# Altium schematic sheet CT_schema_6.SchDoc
size 277 x 170 mm
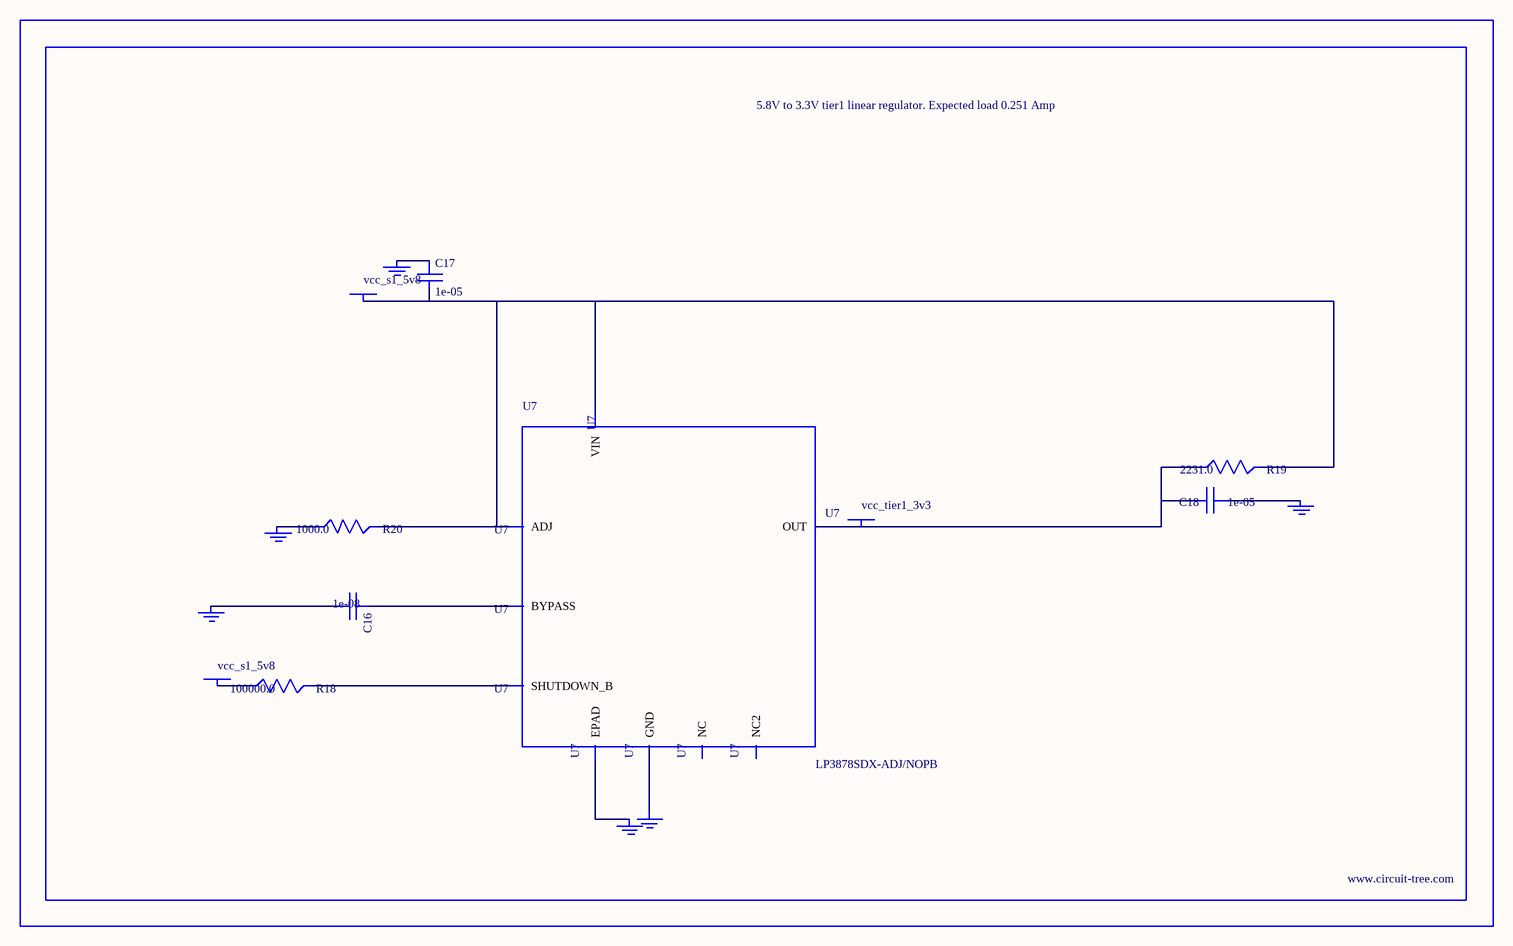
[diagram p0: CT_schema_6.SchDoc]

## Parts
BORDER5  (no value)
C16  1e-08  [C0402]
C17  1e-05  [C1206]
C18  1e-05  [C1210]
GND_INSTANCE_5_0  (no value)
GND_INSTANCE_5_1  (no value)
GND_INSTANCE_5_2  (no value)
GND_INSTANCE_5_3  (no value)
GND_INSTANCE_5_4  (no value)
GND_INSTANCE_5_5  (no value)
POWER_INSTANCE_5_0  vcc_s1_5v8
POWER_INSTANCE_5_1  vcc_s1_5v8
POWER_INSTANCE_5_2  vcc_tier1_3v3
R18  100000.0  [R0603]
R19  2231.0  [R0603]
R20  1000.0  [R0603]
U7  LP3878SDX-ADJ/NOPB  [WSON-8]

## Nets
NetC16_1: C16.1 U7.1(BYPASS)
NetC16_2: C16.2 GND_INSTANCE_5_0.0(GND)
NetC17_1: C17.1 GND_INSTANCE_5_1.0(GND)
NetC17_2: C17.2 POWER_INSTANCE_5_0.0(PWR) R19.2 R20.2 U7.4(VIN) U7.6(ADJ)
NetC18_1: C18.1 GND_INSTANCE_5_2.0(GND)
NetC18_2: C18.2 POWER_INSTANCE_5_2.0(PWR) R19.1 U7.5(OUT)
NetGND_INSTANCE_5_3_0: GND_INSTANCE_5_3.0(GND) R20.1
NetGND_INSTANCE_5_4_0: GND_INSTANCE_5_4.0(GND) U7.PAD(EPAD)
NetGND_INSTANCE_5_5_0: GND_INSTANCE_5_5.0(GND) U7.3(GND)
NetPOWER_INSTANCE_5_1_0: POWER_INSTANCE_5_1.0(PWR) R18.1
NetR18_2: R18.2 U7.8(SHUTDOWN_B)

Not connected (* = marked no-connect by the designer): U7 2(NC) 7(NC2)

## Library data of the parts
BORDER5 = BORDER_PAGE5
C16 = C0402C103K3RAC
C17 = C1206C106K3RACTU
C18 = GRM32DR61E106MA12L
GND_INSTANCE_5_0-GND_INSTANCE_5_5 = GND
POWER_INSTANCE_5_0-POWER_INSTANCE_5_2 = PWR
R18 = RC0603JR-07100KL
R19 = R19
R20 = RC0603JR-071KL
